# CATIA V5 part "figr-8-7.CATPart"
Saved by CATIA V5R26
Part number: Part1
Bounding box of the stored display mesh (mm): x 4.549 to 89.781, y -52.238 to 26.36, z 54 to 147.773
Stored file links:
  D:\_Deepak\CATIA\CATIA V5-6R2016_Deepak\Resources\Part files\Partfiles\c08_catia_v5_6r2016_prt\figr-8-7.CATPart
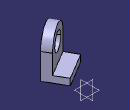
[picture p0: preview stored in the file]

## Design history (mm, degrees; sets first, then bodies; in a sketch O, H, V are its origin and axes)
Body1 (main body)
  Sketch1 on yz-plane, origin (0, 0, 0), H (0, 1, 0), V (0, 0, 1)
    point P1 (-104.4861, 0)
    line L1 (-104.4861, 0) -> (-104.4861, 44.267)
    arc A1 centre (-69.7903, 44.267) radius 34.6958 from (-104.4861, 44.267) to (-35.0946, 44.267) cw
    line L2 (-35.0946, 44.267) -> (-35.0946, 0)
    point P5 (-35.0946, 0)
    line L3 (-35.0946, 0) -> (-104.4861, 0)
    circle A2 centre (-69.7903, 44.267) radius 19.5413
    coincidence: P1 H, P5 H
    vertical: L1 V
    tangency: A1 L1, L2 A1
    horizontal: L3 H
  Pad1: profile Sketch1, direction (1, 0, 0), length 20
  Sketch2 on face of Pad1, origin (0, 0, 0), H (0, -1, 0), V (0, 0, 1)
    point P1 (35.0946, 0)
    line L1 (35.0946, 0) -> (104.4861, 0)
    line L2 (104.4861, 0) -> (104.4861, -15)
    line L3 (104.4861, -15) -> (35.0946, -15)
    line L4 (35.0946, -15) -> (35.0946, 0)
    reference projected line E1 (35.0946, 0) -> (35.0946, 44.267) from edge [face of Pad1 | face of Pad1]
    reference projected line E2 (104.4861, 44.267) -> (104.4861, 0) from edge [face of Pad1 | face of Pad1]
    distance L3 L1 = 15
    coincidence: P1 H, L4 E1, L2 E2
    horizontal: L1 H, L3 H
    vertical: L2 V, L4 V
  Pad2: profile Sketch2, direction (1, 0, 0), length 50
  Translate1: ToTransfor Pad2, Direction xy-plane, Length 69
  Rotate1: ToTransfor Translate1, Axis edge, Angle 121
